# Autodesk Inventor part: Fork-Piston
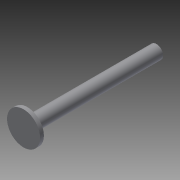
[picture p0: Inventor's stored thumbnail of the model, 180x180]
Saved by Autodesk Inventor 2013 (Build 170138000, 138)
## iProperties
Shininess: 64.0
Length Units: 11272
Angle Units: 11279
Time Units: 11290
Mass Units: 11286
Length Display Precision: 3
Angle Display Precision: 2
Compacted: True
Created: 2001-11
Part Number: Fork-Piston
Document SubType Name: Modeling
Designer: Autodesk, Inc.
Mass: 6.28409 g
Surface Area: 33.2778 cm^2
Volume: 6.28409 cm^3
Density: 1 g/cm^3
Material: Generic
Density: 0.0
Volumn: 0.0
Area: 0.0
PropertySet Name: Model Information
Control State: 0
Master: False
Checked Out: False
Author: Autodesk, Inc.
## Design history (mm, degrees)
sketch "Sketch1"
  geometry: C1 r 10.985 at (6.128, 0) reference
extrude "Extrusion1" new body sketch "Sketch1" distance "d0" = 2.54; taper "d1" = 0 deg
sketch "Sketch2"
  geometry: C1 r 4.445 at (0, 0) reference
extrude "Extrusion2" join sketch "Sketch2" distance "d2" = 85.725; taper "d3" = 0 deg
body "Solid1"
node "Reference1"
node "Reference2"
